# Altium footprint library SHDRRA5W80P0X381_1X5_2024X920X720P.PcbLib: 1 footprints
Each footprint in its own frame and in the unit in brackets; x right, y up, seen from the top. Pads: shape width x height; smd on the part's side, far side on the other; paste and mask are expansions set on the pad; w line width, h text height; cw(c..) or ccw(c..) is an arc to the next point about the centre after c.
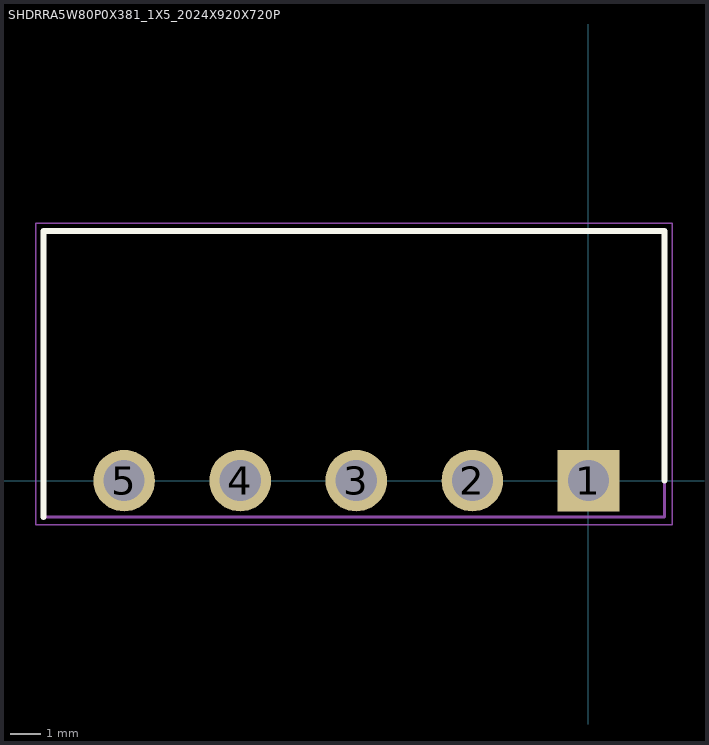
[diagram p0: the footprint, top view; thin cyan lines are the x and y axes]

## SHDRRA5W80P0X381_1X5_2024X920X720P [mm]
pads (5):
  rect 2.025x2.025 / inner round 2.025 / far side rect 2.025x2.025 hole 1.35: 1(0,0)
  round 2.025 hole 1.35: 2(-3.81,0) 3(-7.62,0) 4(-11.43,0) 5(-15.24,0)
Top Overlay:
  lines w0.2: -17.89,-1.2 -17.89,8.2 2.5,8.2 2.5,0
Mechanical 15:
  lines w0.1: -17.89,-1.2 2.5,-1.2 2.5,8.2 -17.89,8.2 -17.89,-1.2
Mechanical 20:
  lines w0.05: -18.14,-1.45 2.75,-1.45 2.75,8.45 -18.14,8.45 -18.14,-1.45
